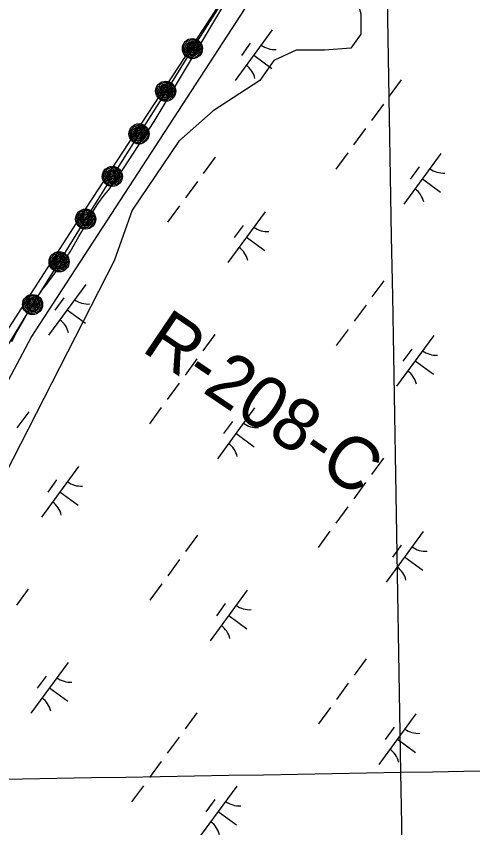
# Model space of a CAD drawing. Extents: x 3905714 to 3926767, y 183354 to 205755.
# Drawn here: x 3914578 to 3914941, y 187283 to 187929 of the extents above; entities that cross this region are included whole.
import ezdxf

# ---------------------------------------------------------------- set-up
doc = ezdxf.new("R2010")
doc.units = 0
for name, color, linetype in [('V-GRID-MAJR', 7, 'Continuous'), ('V-RIVR-EDGE', 7, 'Continuous'), ('V-RIVR-RANG-IDEN', 7, 'Continuous'), ('V-RRAP-FSHR', 7, 'Continuous'), ('V-TOPO-SHOR', 7, 'Continuous'), ('V-WETL-SWMP', 7, 'Continuous')]:
    doc.layers.add(name, color=color, linetype=linetype)

msp = doc.modelspace()

# ---------------------------------------------------------------- linework, layer by layer
at = {"layer": 'V-GRID-MAJR'}
for points in [[(3914930.18, 184667.84), (3914884.14, 187327.39), (3914779.24, 193387.51), (3914694.62, 198275.87)], [(3911382.55, 187266.99), (3914884.14, 187327.39), (3918088.41, 187383)]]:
    msp.add_spline(points, degree=3, dxfattribs=at)
at = {"layer": 'V-RIVR-EDGE'}
for points in [[(3915604.94, 189214.16), (3915307.8, 188778.79), (3915113.05, 188490.69), (3915014.87, 188355.49), (3914997.17, 188316.86), (3914907.04, 188207.42), (3914841.05, 188123.72), (3914771.84, 187996.57), (3914746.09, 187948.29), (3914633.42, 187776.07), (3914490.18, 187553.96), (3914317.96, 187185.39)], [(3914379.12, 187240.11), (3914445.11, 187401.06), (3914589.97, 187673.06), (3914799.2, 187994.96), (3914821.73, 187994.96), (3914841.05, 187969.21), (3914845.88, 187953.12), (3914852.31, 187930.58), (3914852.31, 187914.49), (3914844.27, 187903.22), (3914823.34, 187901.61), (3914800.81, 187901.61), (3914783.1, 187893.57), (3914771.84, 187877.47), (3914734.82, 187853.33), (3914707.46, 187829.19), (3914670.44, 187774.46), (3914655.95, 187734.23), (3914519.15, 187467.05), (3914498.22, 187417.15), (3914470.86, 187359.21), (3914367.04, 187032.03)]]:
    msp.add_lwpolyline(points, dxfattribs=at)
at = {"layer": 'V-RRAP-FSHR'}
for points in [[(3914739.78, 187936.69), (3914718.31, 187902.94), (3914697.68, 187869.46), (3914675.83, 187835.15), (3914654.59, 187801.26), (3914633.38, 187767.34), (3914612.27, 187733.36), (3914591.16, 187699.39), (3914570.56, 187665.41), (3914549.35, 187631.21), (3914531.12, 187595.6), (3914512.89, 187559.99), (3914494.67, 187524.39), (3914475.57, 187489.24), (3914456.37, 187454.15), (3914439.12, 187418.82), (3914422.37, 187381.76), (3914405.62, 187345.43), (3914388.87, 187309.11), (3914372.13, 187272.78)], [(3914720.14, 187910.03), (3914721.96, 187909.03), (3914724.38, 187906.82), (3914725.37, 187904.44), (3914725.26, 187901.23), (3914723.97, 187898.79), (3914721.57, 187896.5), (3914718.69, 187896.09), (3914716.42, 187896), (3914713.94, 187897.38), (3914712.25, 187899.26), (3914711.43, 187901.47), (3914711.26, 187903.68), (3914712, 187906.19), (3914714.34, 187908.76), (3914717.29, 187909.95), (3914719.7, 187909.93), (3914722.16, 187907.42), (3914724.03, 187905.11), (3914724.18, 187902.32), (3914723.07, 187899.29), (3914720.59, 187897.42), (3914717.6, 187897.05), (3914714.95, 187897.95), (3914712.92, 187900.26), (3914712.33, 187903.19), (3914713.5, 187906.43), (3914715.97, 187908.33), (3914718.69, 187908.93), (3914721.59, 187907.22), (3914722.95, 187904.82), (3914723.18, 187901.98), (3914721.94, 187899.51), (3914719.69, 187898.13), (3914716.93, 187898.02), (3914714.42, 187899.91), (3914713.39, 187902.56), (3914714.62, 187906.24), (3914717, 187907.78), (3914718.91, 187907.8), (3914721.19, 187905.75), (3914722.33, 187903.1), (3914721.68, 187900.75), (3914719.25, 187898.92), (3914716.9, 187899.18), (3914714.6, 187901.24), (3914714.56, 187903.65), (3914715.72, 187905.79), (3914717.53, 187906.97), (3914719.53, 187906.47), (3914720.64, 187904.82), (3914721.33, 187902.62), (3914720.33, 187900.8), (3914718.58, 187899.93), (3914716.48, 187900.55), (3914715.51, 187902.2), (3914715.61, 187903.96), (3914717.05, 187905.65), (3914718.37, 187905.83), (3914719.72, 187904.35), (3914720.21, 187902.49), (3914719.48, 187901.26), (3914717.93, 187901.1), (3914716.39, 187902.16), (3914716.54, 187903.79), (3914717.52, 187904.7), (3914718.97, 187903.93), (3914719.2, 187902.3), (3914718.05, 187902.02), (3914717.39, 187902.95), (3914717.66, 187903.75), (3914718.34, 187902.98)], [(3914698.9, 187876.14), (3914700.72, 187875.13), (3914703.14, 187872.93), (3914704.13, 187870.55), (3914704.02, 187867.33), (3914702.73, 187864.89), (3914700.33, 187862.6), (3914697.45, 187862.2), (3914695.18, 187862.1), (3914692.7, 187863.48), (3914691.01, 187865.37), (3914690.19, 187867.58), (3914690.02, 187869.79), (3914690.76, 187872.29), (3914693.1, 187874.87), (3914696.05, 187876.06), (3914698.46, 187876.03), (3914700.92, 187873.52), (3914702.79, 187871.21), (3914702.94, 187868.43), (3914701.83, 187865.39), (3914699.35, 187863.52), (3914696.36, 187863.16), (3914693.71, 187864.06), (3914691.68, 187866.37), (3914691.09, 187869.29), (3914692.26, 187872.53), (3914694.73, 187874.43), (3914697.45, 187875.04), (3914700.35, 187873.33), (3914701.71, 187870.92), (3914701.94, 187868.09), (3914700.7, 187865.62), (3914698.45, 187864.23), (3914695.69, 187864.13), (3914693.18, 187866.01), (3914692.15, 187868.66), (3914693.38, 187872.34), (3914695.77, 187873.89), (3914697.67, 187873.9), (3914699.95, 187871.86), (3914701.08, 187869.21), (3914700.44, 187866.85), (3914698.01, 187865.02), (3914695.66, 187865.29), (3914693.36, 187867.35), (3914693.32, 187869.76), (3914694.48, 187871.89), (3914696.29, 187873.08), (3914698.29, 187872.58), (3914699.4, 187870.92), (3914700.09, 187868.73), (3914699.09, 187866.9), (3914697.33, 187866.03), (3914695.24, 187866.66), (3914694.27, 187868.3), (3914694.37, 187870.07), (3914695.81, 187871.76), (3914697.13, 187871.93), (3914698.48, 187870.46), (3914698.98, 187868.6), (3914698.24, 187867.37), (3914696.69, 187867.2), (3914695.15, 187868.27), (3914695.3, 187869.9), (3914696.28, 187870.8), (3914697.73, 187870.03), (3914697.96, 187868.41), (3914696.81, 187868.12), (3914696.15, 187869.05), (3914696.42, 187869.86), (3914697.1, 187869.08)], [(3914677.66, 187842.24), (3914679.48, 187841.24), (3914681.9, 187839.03), (3914682.89, 187836.65), (3914682.78, 187833.44), (3914681.49, 187831), (3914679.09, 187828.71), (3914676.21, 187828.3), (3914673.94, 187828.21), (3914671.46, 187829.59), (3914669.77, 187831.47), (3914668.95, 187833.68), (3914668.78, 187835.89), (3914669.52, 187838.4), (3914671.86, 187840.97), (3914674.81, 187842.16), (3914677.22, 187842.14), (3914679.68, 187839.63), (3914681.55, 187837.32), (3914681.7, 187834.53), (3914680.59, 187831.49), (3914678.11, 187829.63), (3914675.12, 187829.26), (3914672.47, 187830.16), (3914670.44, 187832.47), (3914669.85, 187835.4), (3914671.02, 187838.64), (3914673.49, 187840.54), (3914676.21, 187841.14), (3914679.11, 187839.43), (3914680.47, 187837.03), (3914680.7, 187834.19), (3914679.46, 187831.72), (3914677.21, 187830.34), (3914674.45, 187830.23), (3914671.94, 187832.12), (3914670.91, 187834.77), (3914672.14, 187838.45), (3914674.53, 187839.99), (3914676.43, 187840.01), (3914678.71, 187837.96), (3914679.85, 187835.31), (3914679.2, 187832.96), (3914676.77, 187831.13), (3914674.42, 187831.39), (3914672.12, 187833.46), (3914672.08, 187835.86), (3914673.24, 187838), (3914675.05, 187839.18), (3914677.06, 187838.68), (3914678.16, 187837.03), (3914678.85, 187834.83), (3914677.85, 187833.01), (3914676.1, 187832.14), (3914674, 187832.76), (3914673.03, 187834.41), (3914673.13, 187836.17), (3914674.57, 187837.86), (3914675.89, 187838.04), (3914677.25, 187836.56), (3914677.73, 187834.7), (3914677, 187833.47), (3914675.45, 187833.31), (3914673.91, 187834.37), (3914674.06, 187836), (3914675.04, 187836.91), (3914676.49, 187836.14), (3914676.72, 187834.51), (3914675.57, 187834.23), (3914674.91, 187835.16), (3914675.18, 187835.96), (3914675.86, 187835.18)], [(3914656.42, 187808.35), (3914658.24, 187807.34), (3914660.66, 187805.14), (3914661.65, 187802.76), (3914661.54, 187799.54), (3914660.25, 187797.11), (3914657.85, 187794.81), (3914654.97, 187794.41), (3914652.7, 187794.31), (3914650.22, 187795.69), (3914648.53, 187797.58), (3914647.71, 187799.79), (3914647.54, 187802), (3914648.28, 187804.5), (3914650.62, 187807.08), (3914653.57, 187808.27), (3914655.98, 187808.24), (3914658.44, 187805.73), (3914660.31, 187803.42), (3914660.46, 187800.64), (3914659.35, 187797.6), (3914656.88, 187795.74), (3914653.88, 187795.37), (3914651.23, 187796.27), (3914649.2, 187798.58), (3914648.61, 187801.5), (3914649.78, 187804.74), (3914652.25, 187806.64), (3914654.97, 187807.25), (3914657.87, 187805.54), (3914659.23, 187803.13), (3914659.46, 187800.3), (3914658.22, 187797.83), (3914655.97, 187796.44), (3914653.21, 187796.34), (3914650.7, 187798.22), (3914649.67, 187800.87), (3914650.9, 187804.55), (3914653.29, 187806.1), (3914655.19, 187806.11), (3914657.47, 187804.07), (3914658.6, 187801.42), (3914657.96, 187799.06), (3914655.53, 187797.23), (3914653.18, 187797.5), (3914650.88, 187799.56), (3914650.84, 187801.97), (3914652, 187804.11), (3914653.81, 187805.29), (3914655.81, 187804.79), (3914656.92, 187803.13), (3914657.61, 187800.93), (3914656.61, 187799.11), (3914654.85, 187798.24), (3914652.76, 187798.87), (3914651.79, 187800.51), (3914651.89, 187802.28), (3914653.33, 187803.96), (3914654.65, 187804.14), (3914656, 187802.67), (3914656.5, 187800.81), (3914655.76, 187799.58), (3914654.21, 187799.41), (3914652.67, 187800.48), (3914652.82, 187802.11), (3914653.8, 187803.01), (3914655.25, 187802.24), (3914655.48, 187800.62), (3914654.33, 187800.33), (3914653.67, 187801.26), (3914653.94, 187802.07), (3914654.62, 187801.29)], [(3914635.19, 187774.44), (3914637.02, 187773.44), (3914639.44, 187771.24), (3914640.44, 187768.86), (3914640.34, 187765.65), (3914639.06, 187763.21), (3914636.67, 187760.91), (3914633.79, 187760.49), (3914631.52, 187760.39), (3914629.04, 187761.76), (3914627.34, 187763.64), (3914626.51, 187765.84), (3914626.33, 187768.05), (3914627.06, 187770.56), (3914629.39, 187773.15), (3914632.34, 187774.35), (3914634.75, 187774.33), (3914637.22, 187771.83), (3914639.1, 187769.53), (3914639.26, 187766.74), (3914638.16, 187763.7), (3914635.69, 187761.83), (3914632.7, 187761.45), (3914630.05, 187762.34), (3914628, 187764.64), (3914627.4, 187767.56), (3914628.56, 187770.81), (3914631.02, 187772.72), (3914633.75, 187773.33), (3914636.65, 187771.63), (3914638.02, 187769.23), (3914638.25, 187766.4), (3914637.03, 187763.93), (3914634.78, 187762.53), (3914632.03, 187762.42), (3914629.51, 187764.29), (3914628.46, 187766.94), (3914629.69, 187770.62), (3914632.06, 187772.18), (3914633.97, 187772.2), (3914636.25, 187770.16), (3914637.4, 187767.52), (3914636.76, 187765.16), (3914634.34, 187763.32), (3914631.99, 187763.58), (3914629.68, 187765.63), (3914629.63, 187768.04), (3914630.79, 187770.18), (3914632.59, 187771.36), (3914634.6, 187770.88), (3914635.71, 187769.22), (3914636.41, 187767.03), (3914635.41, 187765.2), (3914633.66, 187764.33), (3914631.56, 187764.94), (3914630.59, 187766.58), (3914630.68, 187768.35), (3914632.11, 187770.04), (3914633.43, 187770.22), (3914634.79, 187768.76), (3914635.29, 187766.9), (3914634.56, 187765.66), (3914633.01, 187765.49), (3914631.46, 187766.55), (3914631.61, 187768.18), (3914632.59, 187769.09), (3914634.04, 187768.33), (3914634.28, 187766.7), (3914633.13, 187766.41), (3914632.47, 187767.34), (3914632.73, 187768.15), (3914633.42, 187767.37)], [(3914614.08, 187740.46), (3914615.91, 187739.46), (3914618.33, 187737.27), (3914619.33, 187734.89), (3914619.23, 187731.68), (3914617.96, 187729.23), (3914615.56, 187726.93), (3914612.68, 187726.52), (3914610.41, 187726.41), (3914607.93, 187727.78), (3914606.23, 187729.66), (3914605.4, 187731.87), (3914605.22, 187734.08), (3914605.96, 187736.59), (3914608.28, 187739.17), (3914611.23, 187740.37), (3914613.64, 187740.36), (3914616.11, 187737.85), (3914617.99, 187735.55), (3914618.15, 187732.76), (3914617.05, 187729.73), (3914614.58, 187727.85), (3914611.59, 187727.47), (3914608.94, 187728.36), (3914606.89, 187730.67), (3914606.29, 187733.58), (3914607.45, 187736.83), (3914609.91, 187738.74), (3914612.64, 187739.36), (3914615.54, 187737.66), (3914616.91, 187735.26), (3914617.15, 187732.42), (3914615.92, 187729.95), (3914613.67, 187728.55), (3914610.92, 187728.44), (3914608.4, 187730.32), (3914607.35, 187732.96), (3914608.58, 187736.65), (3914610.95, 187738.2), (3914612.86, 187738.22), (3914615.14, 187736.18), (3914616.29, 187733.54), (3914615.65, 187731.18), (3914613.23, 187729.34), (3914610.88, 187729.6), (3914608.57, 187731.65), (3914608.52, 187734.06), (3914609.68, 187736.2), (3914611.48, 187737.39), (3914613.49, 187736.9), (3914614.6, 187735.25), (3914615.3, 187733.05), (3914614.3, 187731.23), (3914612.55, 187730.35), (3914610.46, 187730.97), (3914609.48, 187732.61), (3914609.57, 187734.37), (3914611, 187736.07), (3914612.32, 187736.25), (3914613.69, 187734.78), (3914614.18, 187732.92), (3914613.45, 187731.69), (3914611.9, 187731.52), (3914610.35, 187732.58), (3914610.5, 187734.21), (3914611.48, 187735.12), (3914612.94, 187734.35), (3914613.17, 187732.73), (3914612.02, 187732.44), (3914611.36, 187733.37), (3914611.62, 187734.17), (3914612.31, 187733.4)], [(3914592.97, 187706.48), (3914594.8, 187705.49), (3914597.22, 187703.29), (3914598.22, 187700.91), (3914598.12, 187697.7), (3914596.85, 187695.26), (3914594.45, 187692.96), (3914591.58, 187692.54), (3914589.3, 187692.43), (3914586.82, 187693.81), (3914585.12, 187695.68), (3914584.29, 187697.89), (3914584.11, 187700.1), (3914584.85, 187702.61), (3914587.17, 187705.19), (3914590.12, 187706.39), (3914592.53, 187706.38), (3914595, 187703.88), (3914596.88, 187701.58), (3914597.04, 187698.79), (3914595.95, 187695.75), (3914593.47, 187693.88), (3914590.48, 187693.49), (3914587.83, 187694.38), (3914585.78, 187696.69), (3914585.19, 187699.61), (3914586.34, 187702.85), (3914588.8, 187704.77), (3914591.53, 187705.38), (3914594.43, 187703.68), (3914595.8, 187701.28), (3914596.04, 187698.45), (3914594.81, 187695.97), (3914592.56, 187694.58), (3914589.81, 187694.46), (3914587.29, 187696.34), (3914586.25, 187698.99), (3914587.47, 187702.67), (3914589.84, 187704.22), (3914591.75, 187704.24), (3914594.03, 187702.21), (3914595.18, 187699.56), (3914594.54, 187697.21), (3914592.12, 187695.37), (3914589.77, 187695.62), (3914587.46, 187697.68), (3914587.41, 187700.09), (3914588.57, 187702.23), (3914590.37, 187703.41), (3914592.38, 187702.92), (3914593.49, 187701.27), (3914594.19, 187699.08), (3914593.19, 187697.25), (3914591.44, 187696.38), (3914589.35, 187696.99), (3914588.37, 187698.63), (3914588.46, 187700.4), (3914589.9, 187702.09), (3914591.21, 187702.27), (3914592.58, 187700.8), (3914593.07, 187698.94), (3914592.34, 187697.71), (3914590.79, 187697.54), (3914589.25, 187698.6), (3914589.4, 187700.23), (3914590.37, 187701.14), (3914591.83, 187700.37), (3914592.06, 187698.75), (3914590.91, 187698.46), (3914590.25, 187699.39), (3914590.51, 187700.19), (3914591.2, 187699.42)]]:
    msp.add_lwpolyline(points, dxfattribs=at)
for centre in [(3914718.31, 187902.94), (3914697.07, 187869.05), (3914675.83, 187835.15), (3914654.59, 187801.26), (3914633.38, 187767.34), (3914612.27, 187733.36), (3914591.17, 187699.39)]:
    msp.add_circle(centre, 8, dxfattribs=at)
at = {"layer": 'V-TOPO-SHOR'}
msp.add_lwpolyline([(3914574.78, 187669.88), (3914578.66, 187677.66), (3914583.09, 187685.3), (3914587.38, 187693.08), (3914593.47, 187703.08), (3914598.87, 187710.99), (3914603.3, 187716.55), (3914608.15, 187723.22), (3914611.89, 187727.95), (3914621.03, 187741.28), (3914627.94, 187753.37), (3914632.65, 187761.56), (3914636.66, 187769.34), (3914643.03, 187779.48), (3914648.02, 187786.29), (3914651.62, 187790.32), (3914656.05, 187796.71), (3914663.39, 187807.69), (3914687.89, 187844.92), (3914745.75, 187941.6)], dxfattribs=at)
at = {"layer": 'V-WETL-SWMP'}
for p, q in [((3914687.89, 187844.92), (3914745.75, 187941.6)), ((3914781.82, 187917.89), (3914752.27, 187877.56)), ((3914764.37, 187907.12), (3914757.28, 187897.44)), ((3914767.05, 187897.72), (3914781.57, 187887.08)), ((3914884.37, 187877.99), (3914874.91, 187865.08)), ((3914870.19, 187858.63), (3914860.73, 187845.72)), ((3914663.39, 187807.69), (3914687.89, 187844.92)), ((3914856, 187839.27), (3914846.55, 187826.36)), ((3914841.82, 187819.91), (3914832.36, 187807)), ((3914736.41, 187816.62), (3914726.95, 187803.71)), ((3914916, 187819.58), (3914886.45, 187779.25)), ((3914656.05, 187796.71), (3914663.39, 187807.69)), ((3914898.55, 187808.82), (3914891.46, 187799.14)), ((3914651.62, 187790.32), (3914656.05, 187796.71)), ((3914722.22, 187797.26), (3914712.77, 187784.35)), ((3914901.23, 187799.42), (3914915.75, 187788.78)), ((3914648.02, 187786.29), (3914651.62, 187790.32)), ((3914643.03, 187779.48), (3914648.02, 187786.29)), ((3914636.66, 187769.34), (3914643.03, 187779.48)), ((3914708.04, 187777.9), (3914698.58, 187764.99)), ((3914632.65, 187761.56), (3914636.66, 187769.34)), ((3914776.05, 187773.07), (3914746.5, 187732.73)), ((3914758.59, 187762.3), (3914751.5, 187752.62)), ((3914627.95, 187753.37), (3914632.65, 187761.56)), ((3914621.02, 187741.28), (3914627.95, 187753.37)), ((3914761.27, 187752.9), (3914775.79, 187742.26)), ((3914611.89, 187727.95), (3914621.02, 187741.28)), ((3914603.3, 187716.55), (3914608.15, 187723.22)), ((3914608.15, 187723.22), (3914611.89, 187727.95)), ((3914870.59, 187718.31), (3914861.13, 187705.41)), ((3914593.47, 187703.08), (3914598.87, 187711)), ((3914598.87, 187711), (3914603.3, 187716.55)), ((3914633.51, 187715.45), (3914603.96, 187675.12)), ((3914616.06, 187704.69), (3914608.96, 187695.01)), ((3914587.38, 187693.08), (3914593.47, 187703.08)), ((3914856.4, 187698.95), (3914846.95, 187686.05)), ((3914583.09, 187685.3), (3914587.38, 187693.08)), ((3914618.73, 187695.29), (3914633.25, 187684.65)), ((3914578.66, 187677.66), (3914583.09, 187685.3)), ((3914842.22, 187679.59), (3914832.76, 187666.69)), ((3914574.79, 187669.88), (3914578.66, 187677.66)), ((3914736.06, 187675.55), (3914726.6, 187662.65)), ((3914910.23, 187674.76), (3914880.68, 187634.43)), ((3914892.77, 187664), (3914885.68, 187654.32)), ((3914721.87, 187656.19), (3914712.42, 187643.29)), ((3914895.45, 187654.6), (3914909.97, 187643.96)), ((3914707.69, 187636.83), (3914698.23, 187623.93)), ((3914588.09, 187614.18), (3914578.64, 187601.28)), ((3914693.5, 187617.47), (3914684.05, 187604.57)), ((3914767.69, 187617.15), (3914738.14, 187576.81)), ((3914750.23, 187606.38), (3914743.14, 187596.7)), ((3914752.91, 187596.98), (3914767.43, 187586.34)), ((3914870.24, 187577.25), (3914860.78, 187564.34)), ((3914627.73, 187570.63), (3914598.18, 187530.3)), ((3914610.28, 187559.86), (3914603.19, 187550.18)), ((3914856.05, 187557.89), (3914846.6, 187544.98)), ((3914612.96, 187550.46), (3914627.48, 187539.83)), ((3914841.87, 187538.53), (3914832.41, 187525.62)), ((3914827.68, 187519.17), (3914818.23, 187506.26)), ((3914901.87, 187518.84), (3914872.32, 187478.51)), ((3914722.27, 187515.88), (3914712.82, 187502.97)), ((3914884.41, 187508.07), (3914877.32, 187498.39)), ((3914887.09, 187498.67), (3914901.61, 187488.04)), ((3914708.09, 187496.52), (3914698.63, 187483.61)), ((3914587.74, 187473.12), (3914578.29, 187460.21)), ((3914693.9, 187477.16), (3914684.45, 187464.25)), ((3914761.91, 187472.33), (3914732.36, 187431.99)), ((3914744.46, 187461.56), (3914737.37, 187451.88)), ((3914747.14, 187452.16), (3914761.66, 187441.52)), ((3914619.37, 187414.71), (3914589.82, 187374.38)), ((3914856.45, 187417.57), (3914847, 187404.66)), ((3914601.92, 187403.94), (3914594.83, 187394.26)), ((3914604.6, 187394.54), (3914619.12, 187383.9)), ((3914842.27, 187398.21), (3914832.81, 187385.3)), ((3914721.92, 187374.81), (3914712.47, 187361.91)), ((3914828.08, 187378.85), (3914818.63, 187365.94)), ((3914896.09, 187374.02), (3914866.54, 187333.69)), ((3914878.64, 187363.25), (3914871.55, 187353.57)), ((3914707.74, 187355.45), (3914698.28, 187342.54)), ((3914881.32, 187353.85), (3914895.84, 187343.21)), ((3914693.55, 187336.09), (3914684.1, 187323.18)), ((3914679.37, 187316.73), (3914669.91, 187303.82)), ((3914753.55, 187316.4), (3914724, 187276.07)), ((3914736.1, 187305.64), (3914729.01, 187295.96)), ((3914738.78, 187296.24), (3914753.3, 187285.6))]:
    msp.add_line(p, q, dxfattribs=at)
for centre, start, end in [((3914783.56, 187919.86), 232.99998, 274.54364), ((3914750.91, 187875.3), 12.99998, 54.54364), ((3914917.74, 187821.56), 232.99998, 274.54364), ((3914885.09, 187776.99), 12.99998, 54.54364), ((3914777.79, 187775.04), 232.99998, 274.54364), ((3914745.14, 187730.48), 12.99998, 54.54364), ((3914635.25, 187717.43), 232.99998, 274.54364), ((3914602.6, 187672.86), 12.99998, 54.54364), ((3914911.97, 187676.74), 232.99998, 274.54364), ((3914879.32, 187632.17), 12.99998, 54.54364), ((3914769.43, 187619.12), 232.99998, 274.54364), ((3914736.78, 187574.56), 12.99998, 54.54364), ((3914629.47, 187572.61), 232.99998, 274.54364), ((3914596.83, 187528.04), 12.99998, 54.54364), ((3914903.61, 187520.81), 232.99998, 274.54364), ((3914870.96, 187476.25), 12.99998, 54.54364), ((3914763.65, 187474.3), 232.99998, 274.54364), ((3914731, 187429.74), 12.99998, 54.54364), ((3914621.11, 187416.68), 232.99998, 274.54364), ((3914588.47, 187372.12), 12.99998, 54.54364), ((3914897.83, 187375.99), 232.99998, 274.54364), ((3914865.18, 187331.43), 12.99998, 54.54364), ((3914755.29, 187318.38), 232.99998, 274.54364), ((3914722.64, 187273.81), 12.99998, 54.54364)]:
    msp.add_arc(centre, 17.62, start, end, dxfattribs=at)

# ---------------------------------------------------------------- texts
at = {"layer": 'V-RIVR-RANG-IDEN'}
msp.add_text('R-208-C', height=41.5, rotation=325.96277, dxfattribs=at).set_placement((3914676.85, 187663.05))

doc.saveas('drawing.dxf')
